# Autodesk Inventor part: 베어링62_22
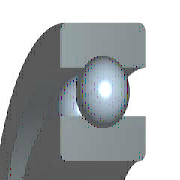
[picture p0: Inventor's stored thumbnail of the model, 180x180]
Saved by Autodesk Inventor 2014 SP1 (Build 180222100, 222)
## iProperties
Created: 2009-02
Part Number: 베어링62_22
Material: 강, 연강
Description: 깊은 그루브 볼 베어링
Document SubType Name: Modeling
Standard: KS B 2023
Designer: KYOUNG IL JANG
Standards Organization: KS
Language: ko-KR
Size Designation: 62/22 - 22 x 50 x 14
Categories: <MemberInstance><Categories><Category DisplayName="샤프트 부품" InternalName="7f7aeb1f-a693-4053-b835-cee3144e0d98" Mnemonic="SHFT"><Category DisplayName="베어링" Inter
Density: 1 g/cm^3
Appearance: 강철
IsCustomPart: 0
Author: KYOUNG IL JANG
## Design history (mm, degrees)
sketch "스케치" dims "d0" = 7.28 (= -0.26 x WD + 0.26 x BD)
  geometry: L1 (3.36, 18)-(10.64, 18); L2 (7, 18)-(7, 14.36); L3 (7, 18)-(7, 21.64); L4 (4.295, 15.564)-(0, 15.564); L5 (0, 11)-(14, 11); L6 (4.295, 20.436)-(0, 20.436); L7 (0, 25)-(14, 25); L8 (14, 11)-(14, 15.564); L9 (9.705, 15.564)-(14, 15.564); L10 (9.705, 20.436)-(14, 20.436); L11 (14, 25)-(14, 20.436); L12 (-1.4, 0)-(8.4, 0) reference; L13 (0, -0.3)-(0, 5.3) reference
  constraints: 22 end point, 4 point on line, 2 collinear, 2 perpendicular, 2 symmetric about line, 1 midpoint, 1 parallel, 14 other
  dimensions: "d9" = 22 diameter of L5 L12 (= WD); "d11" = 50 diameter of L7 L12 (= BD); "d12" = 14 distance between parallel lines of L8 L13 (= KB); "d13" = 31.128 diameter of L9 L12 (= 0.326 x BD + 0.674 x WD)
revolve "본체" stored, may be unused: angle "d6" = 90 deg
revolve "볼" stored, may be unused: angle "d7" = 90 deg
pattern_circular "IDS_ARRAYBALL[SIMPL:T]" dims angle "d3" = 360 deg
body "Solid1"
fillet "모깎기1" dims "d1" = 1 (= KRS)
other parameters: "WD" = 22 [user parameter; used in 5 equation terms], "BD" = 50 [user parameter; used in 5 equation terms], "KB" = 14 [user parameter; used in 1 equation term], "KRS" = 1 [user parameter; used in 1 equation term], "d4" = 0, "d5" = 0, "d8" = 0, "d14" = 0, "d15" = 0, "BBA" = 0 [user parameter], "BC0" = 7154000 [user parameter], "BC" = 1.2233e+07 [user parameter], "BR" = 25 (= 0.5 x BD) [user parameter], "WR" = 11 (= 0.5 x WD) [user parameter]
